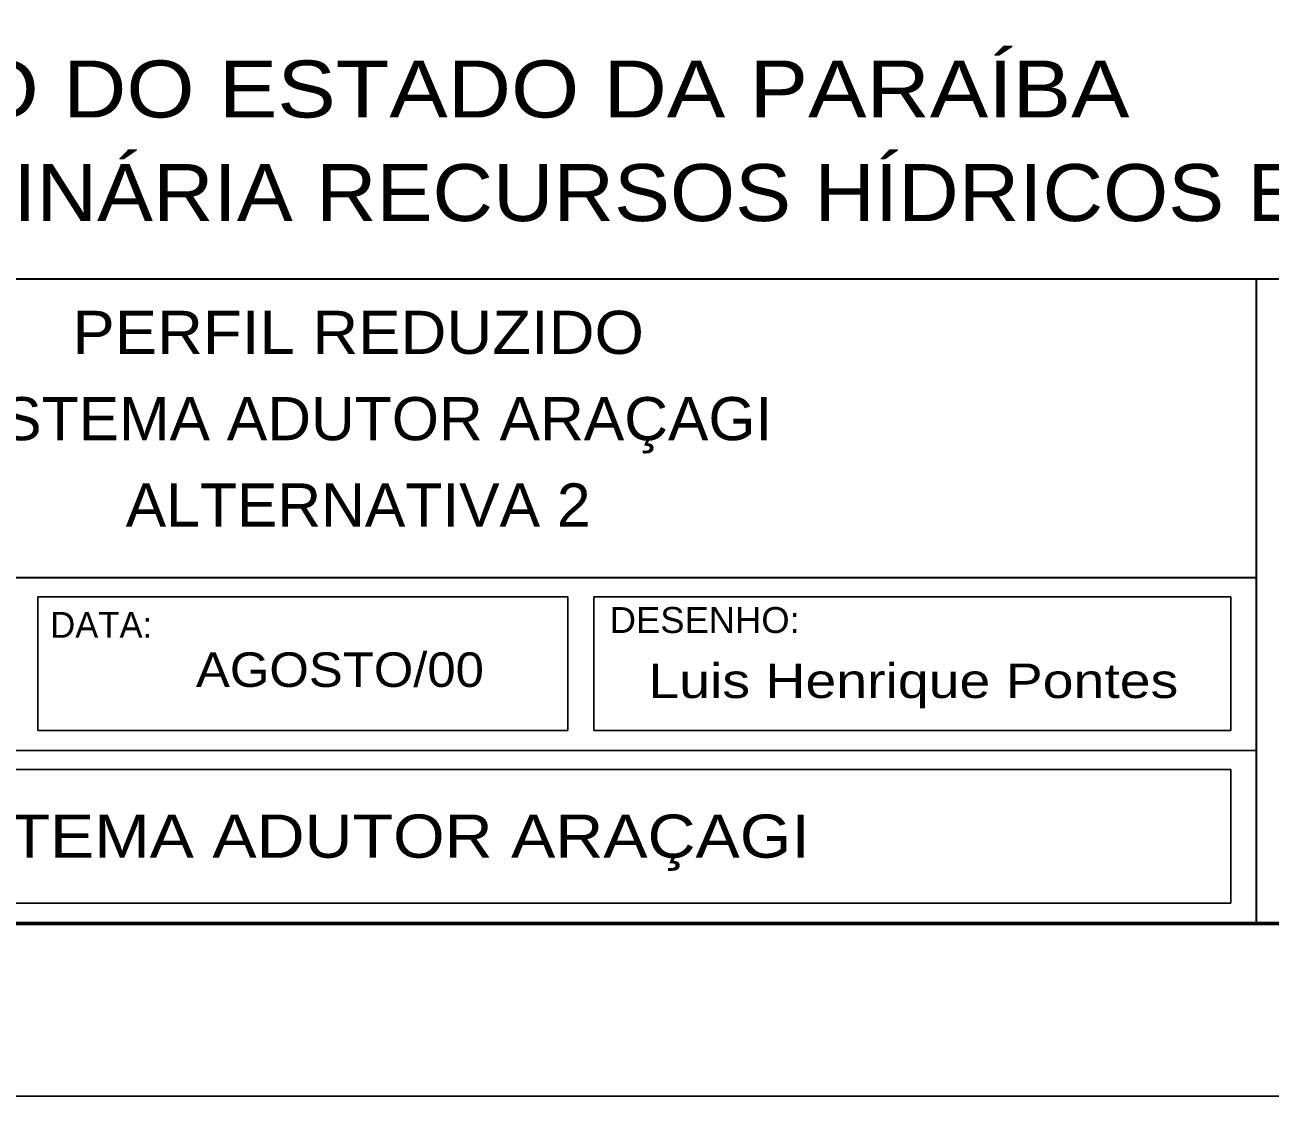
# Model space of a CAD drawing. Extents: x 0 to 1772, y 0 to 1188.
# Drawn here: x 1538 to 1682.2, y -0.1 to 124 of the extents above; entities that cross this region are included whole.
import ezdxf
from ezdxf.enums import TextEntityAlignment as Align

# ---------------------------------------------------------------- set-up
doc = ezdxf.new("R2010")
doc.units = 0
doc.header["$LTSCALE"] = 1.3
doc.layers.add('63', color=7, linetype='Continuous', lineweight=25)

msp = doc.modelspace()

# ---------------------------------------------------------------- linework, layer by layer
at = {"layer": '63', "lineweight": 35}
for p, q in [((1401.833, 94.553), (1751.833, 94.553)), ((1680.653, 19.913), (1680.653, 94.553)), ((1680.653, 59.913), (1473.013, 59.913))]:
    msp.add_line(p, q, dxfattribs=at)
at = {"layer": '63'}
for p, q in [((1600.893, 57.713), (1539.493, 57.713)), ((1539.493, 42.213), (1539.493, 57.713)), ((1539.493, 42.213), (1539.493, 57.713)), ((1600.893, 42.213), (1600.893, 57.713)), ((1677.653, 57.713), (1603.893, 57.713)), ((1603.893, 42.213), (1603.893, 57.713)), ((1677.653, 42.213), (1677.653, 57.713)), ((1539.493, 42.213), (1600.893, 42.213)), ((1603.893, 42.213), (1677.653, 42.213)), ((1680.653, 39.913), (1473.013, 39.913)), ((1677.653, 37.713), (1475.053, 37.713)), ((1677.653, 22.213), (1677.653, 37.713)), ((1475.053, 22.213), (1677.653, 22.213))]:
    msp.add_line(p, q, dxfattribs=at)
for points in [[(-0.167, -0.127), (1771.833, -0.127), (1771.833, 1187.873)], [(-0.167, -0.127), (1771.833, -0.127), (-0.167, -0.127)]]:
    msp.add_lwpolyline(points, dxfattribs=at)
at = {"layer": '63', "lineweight": 60}
msp.add_lwpolyline([(49.833, 1167.873), (1751.833, 1167.873), (1751.833, 19.873), (49.833, 19.873)], close=True, dxfattribs=at)
msp.add_lwpolyline([(1751.833, 184.873), (1751.833, 19.873), (1401.833, 19.873)], dxfattribs=at)

# ---------------------------------------------------------------- texts
at = {"layer": '63'}
for s, height, width, p in [('GOVERNO DO ESTADO DA PARAÍBA', 6.6, 1.15, (1576.823, 113.253)), ('SECRETARIA EXTRAORDINÁRIA RECURSOS HÍDRICOS E MINERAIS', 6.6, 1.1, (1576.833, 101.253)), ('PERFIL REDUZIDO', 5, 1.1, (1576.592, 85.861)), ('SISTEMA ADUTOR ARAÇAGI', 5, 1.05, (1576.592, 75.861)), ('ALTERNATIVA 2', 5, 1.05, (1576.592, 65.861)), ('AGOSTO/00', 4, 1.1, (1574.48, 47.281)), ('Luis Henrique Pontes', 4, 1.2, (1640.893, 45.993)), ('SISTEMA ADUTOR ARAÇAGI', 5, 1.15, (1576.363, 27.493))]:
    msp.add_text(s, height=height, dxfattribs=dict(at, width=width)).set_placement(p, align=Align.CENTER)
at = {"layer": '63', "width": 1.05}
msp.add_text('DESENHO:', height=3, dxfattribs=at).set_placement((1605.733, 53.533))
at = {"layer": '63'}
msp.add_text('DATA:', height=3, dxfattribs=at).set_placement((1546.833, 52.973), align=Align.CENTER)

doc.saveas('drawing.dxf')
